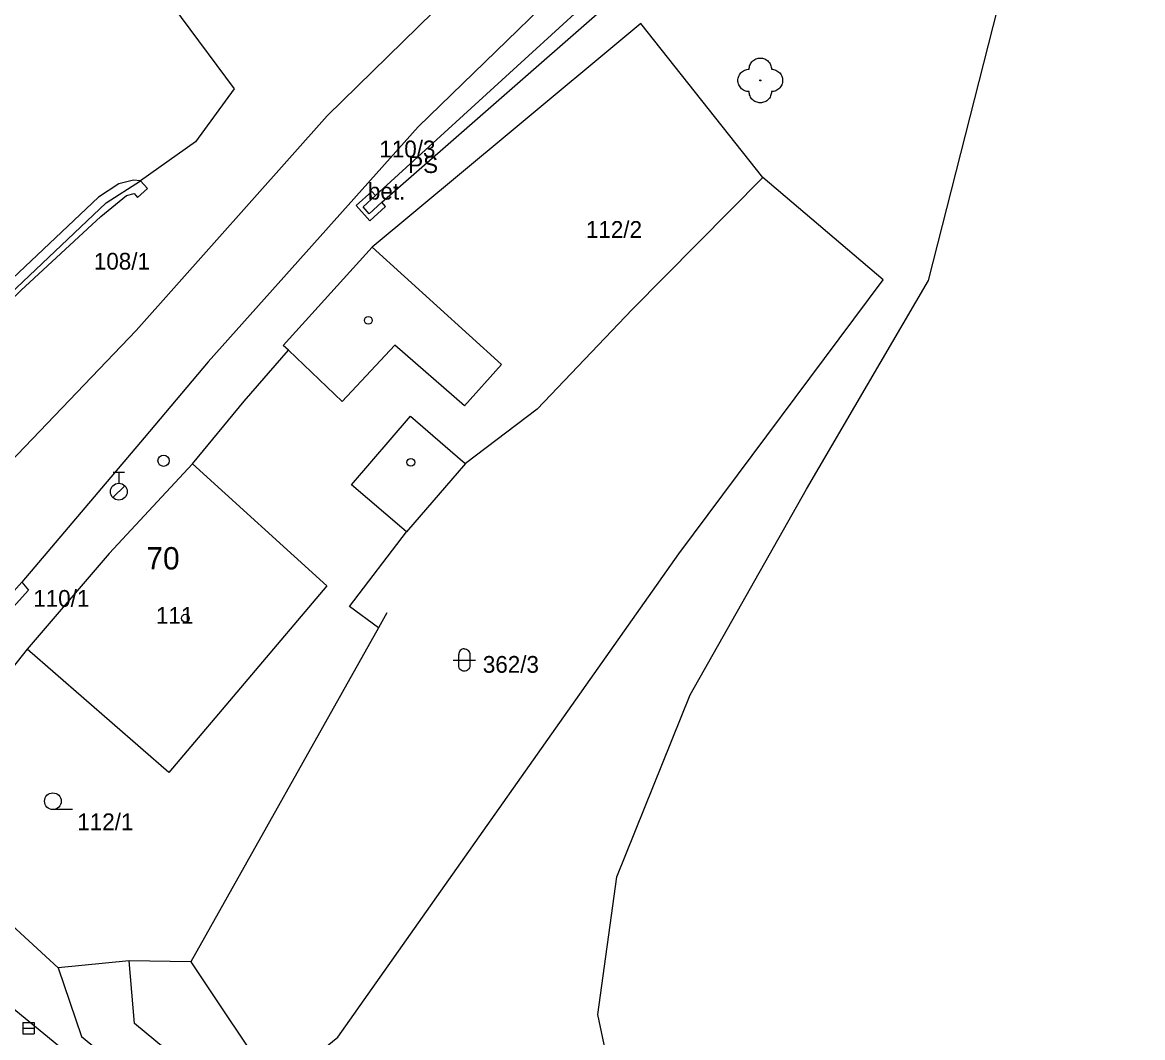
# Model space of a CAD drawing. Extents: x -836568 to -836015, y -1070547 to -1070212.
# Drawn here: x -836491.5 to -836441.4, y -1070322.1 to -1070276.7 of the extents above; entities that cross this region are included whole.
import ezdxf

# ---------------------------------------------------------------- set-up
doc = ezdxf.new("R2010")
doc.units = 0
for name, color, linetype in [('BodPole_mer', 7, 'Continuous'), ('Budovy_hranice', 7, 'Continuous'), ('Budovy_kody', 7, 'Continuous'), ('Doprava_hranice', 7, 'Continuous'), ('OstPloch_hranice', 7, 'Continuous'), ('OstPloch_kody', 7, 'Continuous'), ('PovrZnIS_body', 7, 'Continuous'), ('RuianAdr_popis', 7, 'Continuous'), ('RuianPar_popis', 7, 'Continuous'), ('Stavby_hr_stav', 7, 'Continuous'), ('Stavby_kody', 7, 'Continuous'), ('Stavby_linie', 7, 'Continuous'), ('Vodstvo_hranice', 7, 'Continuous'), ('Vyskopis_linie', 7, 'Continuous'), ('Zelen_body', 7, 'Continuous')]:
    doc.layers.add(name, color=color, linetype=linetype)

msp = doc.modelspace()

# ---------------------------------------------------------------- linework, layer by layer
at = {"layer": 'BodPole_mer'}
for p, q in [((-836463.82, -1070276.71), (-836463.82, -1070276.71)), ((-836458.48, -1070279.26), (-836458.48, -1070279.26)), ((-836482.01, -1070279.63), (-836482.01, -1070279.63)), ((-836477.85, -1070280.85), (-836477.85, -1070280.85)), ((-836473.79, -1070281.33), (-836473.79, -1070281.33)), ((-836469.8, -1070281.7), (-836469.8, -1070281.7)), ((-836483.74, -1070282.01), (-836483.74, -1070282.01)), ((-836486.51, -1070283.72), (-836486.51, -1070283.72)), ((-836486.21, -1070283.75), (-836486.21, -1070283.75)), ((-836458.36, -1070283.6), (-836458.36, -1070283.6)), ((-836487.17, -1070283.89), (-836487.17, -1070283.89)), ((-836486.48, -1070284.32), (-836486.48, -1070284.32)), ((-836485.89, -1070284.09), (-836485.89, -1070284.09)), ((-836475.86, -1070284.22), (-836475.86, -1070284.22)), ((-836488.08, -1070284.48), (-836488.08, -1070284.48)), ((-836487.74, -1070284.74), (-836487.74, -1070284.74)), ((-836486.83, -1070284.4), (-836486.83, -1070284.4)), ((-836486.34, -1070284.49), (-836486.34, -1070284.49)), ((-836476.56, -1070284.86), (-836476.56, -1070284.86)), ((-836475.69, -1070284.41), (-836475.69, -1070284.41)), ((-836475.41, -1070284.71), (-836475.41, -1070284.71)), ((-836487.98, -1070285.34), (-836487.98, -1070285.34)), ((-836476.25, -1070284.92), (-836476.25, -1070284.92)), ((-836475.98, -1070285.22), (-836475.98, -1070285.22)), ((-836475.24, -1070284.9), (-836475.24, -1070284.9)), ((-836475.94, -1070285.54), (-836475.94, -1070285.54)), ((-836475.84, -1070286.72), (-836475.84, -1070286.72)), ((-836452.98, -1070288.18), (-836452.98, -1070288.18)), ((-836450.95, -1070288.2), (-836450.95, -1070288.2)), ((-836464.21, -1070289.51), (-836464.21, -1070289.51)), ((-836486.39, -1070290.44), (-836486.39, -1070290.44)), ((-836479.82, -1070291.11), (-836479.82, -1070291.11)), ((-836479.59, -1070291.33), (-836479.59, -1070291.33)), ((-836474.82, -1070291.1), (-836474.82, -1070291.1)), ((-836483.18, -1070291.85), (-836483.18, -1070291.85)), ((-836470.06, -1070291.96), (-836470.06, -1070291.96)), ((-836481.56, -1070293.61), (-836481.56, -1070293.61)), ((-836477.18, -1070293.62), (-836477.18, -1070293.62)), ((-836471.71, -1070293.81), (-836471.71, -1070293.81)), ((-836474.12, -1070294.28), (-836474.12, -1070294.28)), ((-836468.46, -1070293.96), (-836468.46, -1070293.96)), ((-836486.04, -1070295.25), (-836486.04, -1070295.25)), ((-836485.17, -1070296.27), (-836485.17, -1070296.27)), ((-836483.87, -1070296.4), (-836483.87, -1070296.4)), ((-836471.8, -1070296.28), (-836471.8, -1070296.28)), ((-836471.67, -1070296.39), (-836471.67, -1070296.39)), ((-836476.76, -1070297.35), (-836476.76, -1070297.35)), ((-836487.17, -1070297.65), (-836487.17, -1070297.65)), ((-836456.41, -1070297.54), (-836456.41, -1070297.54)), ((-836474.52, -1070299.27), (-836474.52, -1070299.27)), ((-836474.31, -1070299.45), (-836474.31, -1070299.45)), ((-836487.6, -1070300.42), (-836487.6, -1070300.42)), ((-836462.13, -1070300.43), (-836462.13, -1070300.43)), ((-836477.87, -1070301.86), (-836477.87, -1070301.86)), ((-836491.21, -1070302.05), (-836491.21, -1070302.05)), ((-836476.86, -1070302.79), (-836476.86, -1070302.79)), ((-836475.18, -1070303.07), (-836475.18, -1070303.07)), ((-836475.56, -1070303.74), (-836475.56, -1070303.74)), ((-836491.27, -1070304.7), (-836491.27, -1070304.7)), ((-836461.62, -1070306.74), (-836461.62, -1070306.74)), ((-836484.93, -1070310.21), (-836484.93, -1070310.21)), ((-836464.89, -1070314.87), (-836464.89, -1070314.87)), ((-836489.89, -1070318.94), (-836489.89, -1070318.94)), ((-836486.71, -1070318.63), (-836486.71, -1070318.63)), ((-836483.95, -1070318.68), (-836483.95, -1070318.68)), ((-836486.47, -1070321.44), (-836486.47, -1070321.44)), ((-836465.74, -1070321.03), (-836465.74, -1070321.03)), ((-836491.21, -1070321.64), (-836491.21, -1070321.64)), ((-836488.84, -1070322.01), (-836488.84, -1070322.01)), ((-836477.38, -1070322.05), (-836477.38, -1070322.05))]:
    msp.add_line(p, q, dxfattribs=at)
at = {"layer": 'Budovy_hranice'}
for p, q in [((-836475.84, -1070286.72), (-836479.82, -1070291.11)), ((-836487.6, -1070300.42), (-836491.27, -1070304.7))]:
    msp.add_line(p, q, dxfattribs=at)
for points in [[(-836475.84, -1070286.72), (-836470.06, -1070291.96), (-836471.71, -1070293.81), (-836474.82, -1070291.1), (-836477.18, -1070293.62), (-836479.59, -1070291.33), (-836479.82, -1070291.11)], [(-836474.31, -1070299.45), (-836474.52, -1070299.27), (-836476.76, -1070297.35), (-836474.12, -1070294.28), (-836471.8, -1070296.28), (-836471.67, -1070296.39), (-836474.31, -1070299.45)], [(-836487.6, -1070300.42), (-836483.87, -1070296.4), (-836477.87, -1070301.86), (-836484.93, -1070310.21), (-836491.27, -1070304.7)]]:
    msp.add_lwpolyline(points, dxfattribs=at)
at = {"layer": 'Budovy_kody'}
for centre in [(-836476.01, -1070289.99), (-836474.11, -1070296.34), (-836484.2, -1070303.31)]:
    msp.add_circle(centre, 0.175, dxfattribs=at)
at = {"layer": 'Doprava_hranice'}
for points in [[(-836463.13, -1070260.78), (-836461.66, -1070261.68), (-836460.5, -1070262.24), (-836459.09, -1070262.17), (-836456.22, -1070259.67), (-836453.89, -1070261.93), (-836464.34, -1070272.16), (-836473.79, -1070281.33)], [(-836463.13, -1070260.78), (-836466.54, -1070263.19), (-836466.2, -1070265.91), (-836466.63, -1070266.39), (-836466.02, -1070267.34), (-836466.37, -1070268.96), (-836467.68, -1070270.88), (-836477.85, -1070280.85), (-836486.39, -1070290.44)], [(-836473.79, -1070281.33), (-836483.18, -1070291.85), (-836486.04, -1070295.25)], [(-836486.39, -1070290.44), (-836494.37, -1070298.76), (-836499.1, -1070302.73), (-836502.92, -1070305.55), (-836506.93, -1070308.25), (-836509.27, -1070309.72), (-836512.75, -1070311.69), (-836519.45, -1070314.99), (-836521.21, -1070315.81), (-836530.36, -1070319.04)], [(-836486.04, -1070295.25), (-836491.51, -1070301.7), (-836496.11, -1070306.84), (-836497.41, -1070308.37), (-836498.02, -1070309.18), (-836498.47, -1070310.1), (-836498.73, -1070311.08), (-836498.85, -1070312.07), (-836498.78, -1070313.12), (-836498.51, -1070314.1), (-836498.1, -1070315.03), (-836497.52, -1070315.85), (-836497.01, -1070316.45), (-836496.48, -1070317), (-836489.02, -1070323.12), (-836476.76, -1070333.19), (-836472.89, -1070336.35), (-836460.9, -1070346.19), (-836457.02, -1070349.36), (-836453.9, -1070351.88), (-836451.54, -1070353.74), (-836449.19, -1070355.59), (-836447.61, -1070356.83), (-836445.19, -1070358.65)]]:
    msp.add_lwpolyline(points, dxfattribs=at)
at = {"layer": 'OstPloch_hranice'}
for points in [[(-836464.81, -1070325.47), (-836465.74, -1070321.03), (-836464.89, -1070314.87), (-836461.62, -1070306.74), (-836456.41, -1070297.54), (-836450.95, -1070288.2), (-836447.03, -1070272.79), (-836441.38, -1070260.76)], [(-836491.51, -1070301.7), (-836491.21, -1070302.05), (-836495.74, -1070307.06), (-836496.11, -1070306.84)]]:
    msp.add_lwpolyline(points, dxfattribs=at)
at = {"layer": 'OstPloch_kody'}
for p, q in [((-836471.97, -1070305.43), (-836471.97, -1070304.93)), ((-836471.47, -1070304.93), (-836471.47, -1070305.43)), ((-836472.22, -1070305.18), (-836471.22, -1070305.18)), ((-836489.245, -1070311.87), (-836490.12, -1070311.87))]:
    msp.add_line(p, q, dxfattribs=at)
for points in [[(-836471.72, -1070304.68), (-836471.765, -1070304.684), (-836471.812, -1070304.698), (-836471.857, -1070304.721), (-836471.897, -1070304.753), (-836471.929, -1070304.793), (-836471.952, -1070304.838), (-836471.966, -1070304.885), (-836471.97, -1070304.93)], [(-836471.72, -1070304.68), (-836471.675, -1070304.684), (-836471.628, -1070304.698), (-836471.583, -1070304.721), (-836471.543, -1070304.753), (-836471.511, -1070304.793), (-836471.488, -1070304.838), (-836471.474, -1070304.885), (-836471.47, -1070304.93)], [(-836471.72, -1070305.68), (-836471.765, -1070305.676), (-836471.812, -1070305.662), (-836471.857, -1070305.639), (-836471.897, -1070305.607), (-836471.929, -1070305.567), (-836471.952, -1070305.522), (-836471.966, -1070305.475), (-836471.97, -1070305.43)], [(-836471.47, -1070305.43), (-836471.474, -1070305.475), (-836471.488, -1070305.522), (-836471.511, -1070305.567), (-836471.543, -1070305.607), (-836471.583, -1070305.639), (-836471.628, -1070305.662), (-836471.675, -1070305.676), (-836471.72, -1070305.68)]]:
    msp.add_lwpolyline(points, dxfattribs=at)
msp.add_ellipse((-836490.12, -1070311.495), major_axis=(0.375, 0), ratio=0.999999, dxfattribs=at)
at = {"layer": 'PovrZnIS_body'}
for p, q in [((-836487.42, -1070296.775), (-836486.92, -1070296.775)), ((-836487.17, -1070296.775), (-836487.17, -1070297.275)), ((-836486.905, -1070297.385), (-836487.435, -1070297.915)), ((-836491.46, -1070321.39), (-836490.96, -1070321.39)), ((-836491.46, -1070321.39), (-836491.46, -1070321.89)), ((-836490.96, -1070321.39), (-836490.96, -1070321.89)), ((-836491.46, -1070321.64), (-836490.96, -1070321.64)), ((-836491.46, -1070321.89), (-836490.96, -1070321.89))]:
    msp.add_line(p, q, dxfattribs=at)
for centre, radius in [((-836485.17, -1070296.27), 0.25), ((-836487.17, -1070297.65), 0.375)]:
    msp.add_circle(centre, radius, dxfattribs=at)
at = {"layer": 'RuianAdr_popis'}
msp.add_line((-836485.94, -1070301.13), (-836485.94, -1070301.13), dxfattribs=at)
at = {"layer": 'RuianPar_popis'}
for p, q in [((-836475.52, -1070282.7), (-836475.52, -1070282.7)), ((-836466.28, -1070286.3), (-836466.28, -1070286.3)), ((-836488.29, -1070287.72), (-836488.29, -1070287.72)), ((-836491, -1070302.8), (-836491, -1070302.8)), ((-836485.51, -1070303.56), (-836485.51, -1070303.56)), ((-836470.89, -1070305.75), (-836470.89, -1070305.75)), ((-836489.03, -1070312.79), (-836489.03, -1070312.79))]:
    msp.add_line(p, q, dxfattribs=at)
at = {"layer": 'Stavby_hr_stav'}
for points in [[(-836475.41, -1070284.71), (-836465.3, -1070275.87), (-836465.76, -1070275.33), (-836475.69, -1070284.41)], [(-836475.86, -1070284.22), (-836476.56, -1070284.86), (-836475.94, -1070285.54), (-836475.24, -1070284.9), (-836475.41, -1070284.71), (-836475.98, -1070285.22), (-836476.25, -1070284.92), (-836475.69, -1070284.41), (-836475.86, -1070284.22)]]:
    msp.add_lwpolyline(points, dxfattribs=at)
at = {"layer": 'Stavby_linie'}
for p, q in [((-836463.82, -1070276.71), (-836469.8, -1070281.7)), ((-836458.36, -1070283.6), (-836463.82, -1070276.71)), ((-836469.8, -1070281.7), (-836475.84, -1070286.72)), ((-836481.56, -1070293.61), (-836479.59, -1070291.33)), ((-836483.87, -1070296.4), (-836481.56, -1070293.61)), ((-836476.86, -1070302.79), (-836474.31, -1070299.45)), ((-836475.56, -1070303.74), (-836476.86, -1070302.79))]:
    msp.add_line(p, q, dxfattribs=at)
for points in [[(-836521.92, -1070312.95), (-836519.9, -1070312.2), (-836512.67, -1070307.44), (-836507.45, -1070303.71), (-836506.51, -1070302.98), (-836501.2, -1070297.48), (-836487.74, -1070284.74), (-836486.21, -1070283.75)], [(-836483.95, -1070318.68), (-836480.18, -1070324.33), (-836477.38, -1070322.05), (-836462.13, -1070300.43), (-836452.98, -1070288.18), (-836458.36, -1070283.6)], [(-836458.36, -1070283.6), (-836464.21, -1070289.51), (-836468.46, -1070293.96), (-836471.67, -1070296.39)], [(-836475.18, -1070303.07), (-836475.56, -1070303.74), (-836483.95, -1070318.68)], [(-836491.27, -1070304.7), (-836497.22, -1070312.21), (-836489.89, -1070318.94)], [(-836483.95, -1070318.68), (-836486.71, -1070318.63), (-836489.89, -1070318.94)]]:
    msp.add_lwpolyline(points, dxfattribs=at)
at = {"layer": 'Vodstvo_hranice'}
for points in [[(-836525.34, -1070271.43), (-836521.88, -1070269.71), (-836516.37, -1070264.96), (-836510.93, -1070262.08), (-836507.11, -1070259.33), (-836503.08, -1070256.96), (-836500.52, -1070256.76), (-836498.86, -1070256.68), (-836495.87, -1070257.41), (-836493.93, -1070263.56), (-836492.75, -1070265.06), (-836486.76, -1070273.24), (-836482.01, -1070279.63), (-836483.74, -1070282.01), (-836486.21, -1070283.75)], [(-836538.28, -1070299.17), (-836536.67, -1070302.12), (-836537.27, -1070302.49), (-836535.82, -1070305.08), (-836535.28, -1070304.8), (-836529.27, -1070315.73), (-836524.75, -1070314.46), (-836523.12, -1070313.78), (-836521.89, -1070313.32), (-836519.48, -1070312.36), (-836516.81, -1070310.51), (-836511.44, -1070307.01), (-836506.56, -1070303.42), (-836500.78, -1070297.61), (-836491.56, -1070288.65), (-836487.98, -1070285.34), (-836486.83, -1070284.4), (-836486.48, -1070284.32), (-836486.34, -1070284.49), (-836485.89, -1070284.09), (-836486.21, -1070283.75)], [(-836486.21, -1070283.75), (-836486.51, -1070283.72), (-836487.17, -1070283.89), (-836488.08, -1070284.48), (-836496.59, -1070292.51), (-836502.23, -1070298.08), (-836506.71, -1070302.82), (-836509.99, -1070305.26), (-836517.14, -1070310.02), (-836520.29, -1070312.03), (-836522.22, -1070312.76)]]:
    msp.add_lwpolyline(points, dxfattribs=at)
at = {"layer": 'Vyskopis_linie'}
for points in [[(-836489.89, -1070318.94), (-836488.84, -1070322.01), (-836476.94, -1070331.8), (-836469.67, -1070324.15), (-836470.42, -1070323.81)], [(-836470.42, -1070323.81), (-836476.76, -1070329.47), (-836486.47, -1070321.44), (-836486.71, -1070318.63)]]:
    msp.add_lwpolyline(points, dxfattribs=at)
at = {"layer": 'Zelen_body'}
msp.add_line((-836458.48, -1070279.26), (-836458.48, -1070279.26), dxfattribs=at)
for points in [[(-836458.98, -1070278.76), (-836458.978, -1070278.712), (-836458.97, -1070278.663), (-836458.958, -1070278.613), (-836458.94, -1070278.564), (-836458.916, -1070278.515), (-836458.887, -1070278.469), (-836458.853, -1070278.426), (-836458.814, -1070278.387), (-836458.771, -1070278.353), (-836458.725, -1070278.324), (-836458.676, -1070278.3), (-836458.627, -1070278.282), (-836458.577, -1070278.27), (-836458.528, -1070278.262), (-836458.48, -1070278.26), (-836458.432, -1070278.262), (-836458.383, -1070278.27), (-836458.333, -1070278.282), (-836458.284, -1070278.3), (-836458.235, -1070278.324), (-836458.189, -1070278.353), (-836458.146, -1070278.387), (-836458.107, -1070278.426), (-836458.073, -1070278.469), (-836458.044, -1070278.515), (-836458.02, -1070278.564), (-836458.002, -1070278.613), (-836457.99, -1070278.663), (-836457.982, -1070278.712), (-836457.98, -1070278.76)], [(-836458.98, -1070279.76), (-836459.028, -1070279.758), (-836459.077, -1070279.75), (-836459.127, -1070279.738), (-836459.176, -1070279.72), (-836459.225, -1070279.696), (-836459.271, -1070279.667), (-836459.314, -1070279.633), (-836459.353, -1070279.594), (-836459.387, -1070279.551), (-836459.416, -1070279.505), (-836459.44, -1070279.456), (-836459.458, -1070279.407), (-836459.47, -1070279.357), (-836459.478, -1070279.308), (-836459.48, -1070279.26), (-836459.478, -1070279.212), (-836459.47, -1070279.163), (-836459.458, -1070279.113), (-836459.44, -1070279.064), (-836459.416, -1070279.015), (-836459.387, -1070278.969), (-836459.353, -1070278.926), (-836459.314, -1070278.887), (-836459.271, -1070278.853), (-836459.225, -1070278.824), (-836459.176, -1070278.8), (-836459.127, -1070278.782), (-836459.077, -1070278.77), (-836459.028, -1070278.762), (-836458.98, -1070278.76)], [(-836457.98, -1070278.76), (-836457.932, -1070278.762), (-836457.883, -1070278.77), (-836457.833, -1070278.782), (-836457.784, -1070278.8), (-836457.735, -1070278.824), (-836457.689, -1070278.853), (-836457.646, -1070278.887), (-836457.607, -1070278.926), (-836457.573, -1070278.969), (-836457.544, -1070279.015), (-836457.52, -1070279.064), (-836457.502, -1070279.113), (-836457.49, -1070279.163), (-836457.482, -1070279.212), (-836457.48, -1070279.26), (-836457.482, -1070279.308), (-836457.49, -1070279.357), (-836457.502, -1070279.407), (-836457.52, -1070279.456), (-836457.544, -1070279.505), (-836457.573, -1070279.551), (-836457.607, -1070279.594), (-836457.646, -1070279.633), (-836457.689, -1070279.667), (-836457.735, -1070279.696), (-836457.784, -1070279.72), (-836457.833, -1070279.738), (-836457.883, -1070279.75), (-836457.932, -1070279.758), (-836457.98, -1070279.76)], [(-836457.98, -1070279.76), (-836457.982, -1070279.808), (-836457.99, -1070279.857), (-836458.002, -1070279.907), (-836458.02, -1070279.956), (-836458.044, -1070280.005), (-836458.073, -1070280.051), (-836458.107, -1070280.094), (-836458.146, -1070280.133), (-836458.189, -1070280.167), (-836458.235, -1070280.196), (-836458.284, -1070280.22), (-836458.333, -1070280.238), (-836458.383, -1070280.25), (-836458.432, -1070280.258), (-836458.48, -1070280.26), (-836458.528, -1070280.258), (-836458.577, -1070280.25), (-836458.627, -1070280.238), (-836458.676, -1070280.22), (-836458.725, -1070280.196), (-836458.771, -1070280.167), (-836458.814, -1070280.133), (-836458.853, -1070280.094), (-836458.887, -1070280.051), (-836458.916, -1070280.005), (-836458.94, -1070279.956), (-836458.958, -1070279.907), (-836458.97, -1070279.857), (-836458.978, -1070279.808), (-836458.98, -1070279.76)]]:
    msp.add_lwpolyline(points, dxfattribs=at)
msp.add_ellipse((-836458.48, -1070279.26), major_axis=(0.025, 0), ratio=0.999997, dxfattribs=at)

# ---------------------------------------------------------------- texts
at = {"layer": 'RuianAdr_popis'}
msp.add_text('70', height=1, dxfattribs=at).set_placement((-836485.94, -1070301.13))
at = {"layer": 'RuianPar_popis'}
for s, p in [('110/3', (-836475.52, -1070282.7)), ('112/2', (-836466.28, -1070286.3)), ('108/1', (-836488.29, -1070287.72)), ('110/1', (-836491, -1070302.8)), ('111', (-836485.51, -1070303.56)), ('362/3', (-836470.89, -1070305.75)), ('112/1', (-836489.03, -1070312.79))]:
    msp.add_text(s, height=0.75, dxfattribs=at).set_placement(p)
at = {"layer": 'Stavby_kody'}
for s, p in [('PS', (-836474.23, -1070283.4)), ('bet.', (-836476.03, -1070284.59))]:
    msp.add_text(s, height=0.75, dxfattribs=at).set_placement(p)

doc.saveas('drawing.dxf')
